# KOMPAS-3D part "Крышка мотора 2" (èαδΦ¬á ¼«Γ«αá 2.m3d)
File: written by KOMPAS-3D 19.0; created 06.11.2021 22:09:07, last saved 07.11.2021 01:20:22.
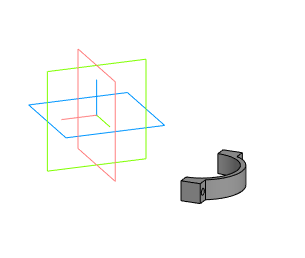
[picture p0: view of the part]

Document properties: Полное имя файла: D:\3D_print\3D проекты Компас 3D\Редуктор (Снова)\Крышка мотора 2.m3d

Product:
- Part/product: Крышка мотора 2
    Масса: 0.0176424

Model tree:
1. Эскиз:1  (with: Элемент выдавливания:5, Элемент выдавливания:2)  (labels: Держатель мотора 36мм; Крышка мотора 2)
2. Элемент выдавливания:1  (with: Элемент выдавливания:6)  (labels: Держатель мотора 36мм; Крышка мотора 2)
     Расстояние 1 = -10
3. Эскиз:2  (with: Элемент выдавливания:1, Элемент выдавливания:6)  (labels: Крышка мотора 2)
4. Элемент выдавливания:2

Referenced files in D:\3D_print\3D проекты Компас 3D\Редуктор (Снова)\: Намоточный станок (Projects 6).a3d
